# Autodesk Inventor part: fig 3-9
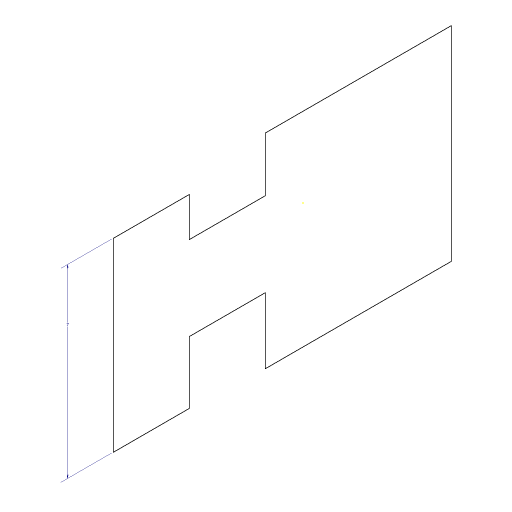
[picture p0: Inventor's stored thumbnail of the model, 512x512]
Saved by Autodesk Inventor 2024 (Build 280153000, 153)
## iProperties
Created: 2018-03
Part Number: fig 3-9
Material: Generic
Document SubType Name: Modeling
Designer: CADCIM 00
Density: 1 g/cm^3
Appearance: Default
Author: CADCIM 00
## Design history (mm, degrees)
sketch "Sketch1"
  geometry: L1 (-4.566, 7.164)-(2.434, 7.164); L2 (2.434, 7.164)-(2.434, 4.293); L3 (2.434, 4.293)-(0.957, 4.293); L4 (0.957, 4.293)-(0.957, 1.422); L5 (0.957, 1.422)-(3.008, 1.422); L6 (3.008, 1.422)-(3.008, -5.605); L7 (3.008, -5.605)-(-4.703, -5.605); L8 (-4.703, -5.605)-(-4.703, 1.422); L9 (-4.703, 1.422)-(-2.215, 1.422); L10 (-2.215, 1.422)-(-2.215, 4.293); L11 (-2.215, 4.293)-(-4.566, 4.293); L12 (-4.566, 4.293)-(-4.566, 7.164); 1 further point
  constraints: 24 end point, 9 perpendicular, 4 point on line, 1 horizontal
  dimensions: "d0" = 7 distance of L1.start L1.end
